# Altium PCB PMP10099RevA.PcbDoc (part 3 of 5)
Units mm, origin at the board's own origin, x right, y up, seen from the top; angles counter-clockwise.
Board outline 227.58 x 89.92 mm, 2 copper layers (Top Layer, Bottom Layer), stack 1.575 mm thick; 558 components, 261 nets, 1374 pads, 560 vias.
Unrouted connection lines stored in the file: 7.
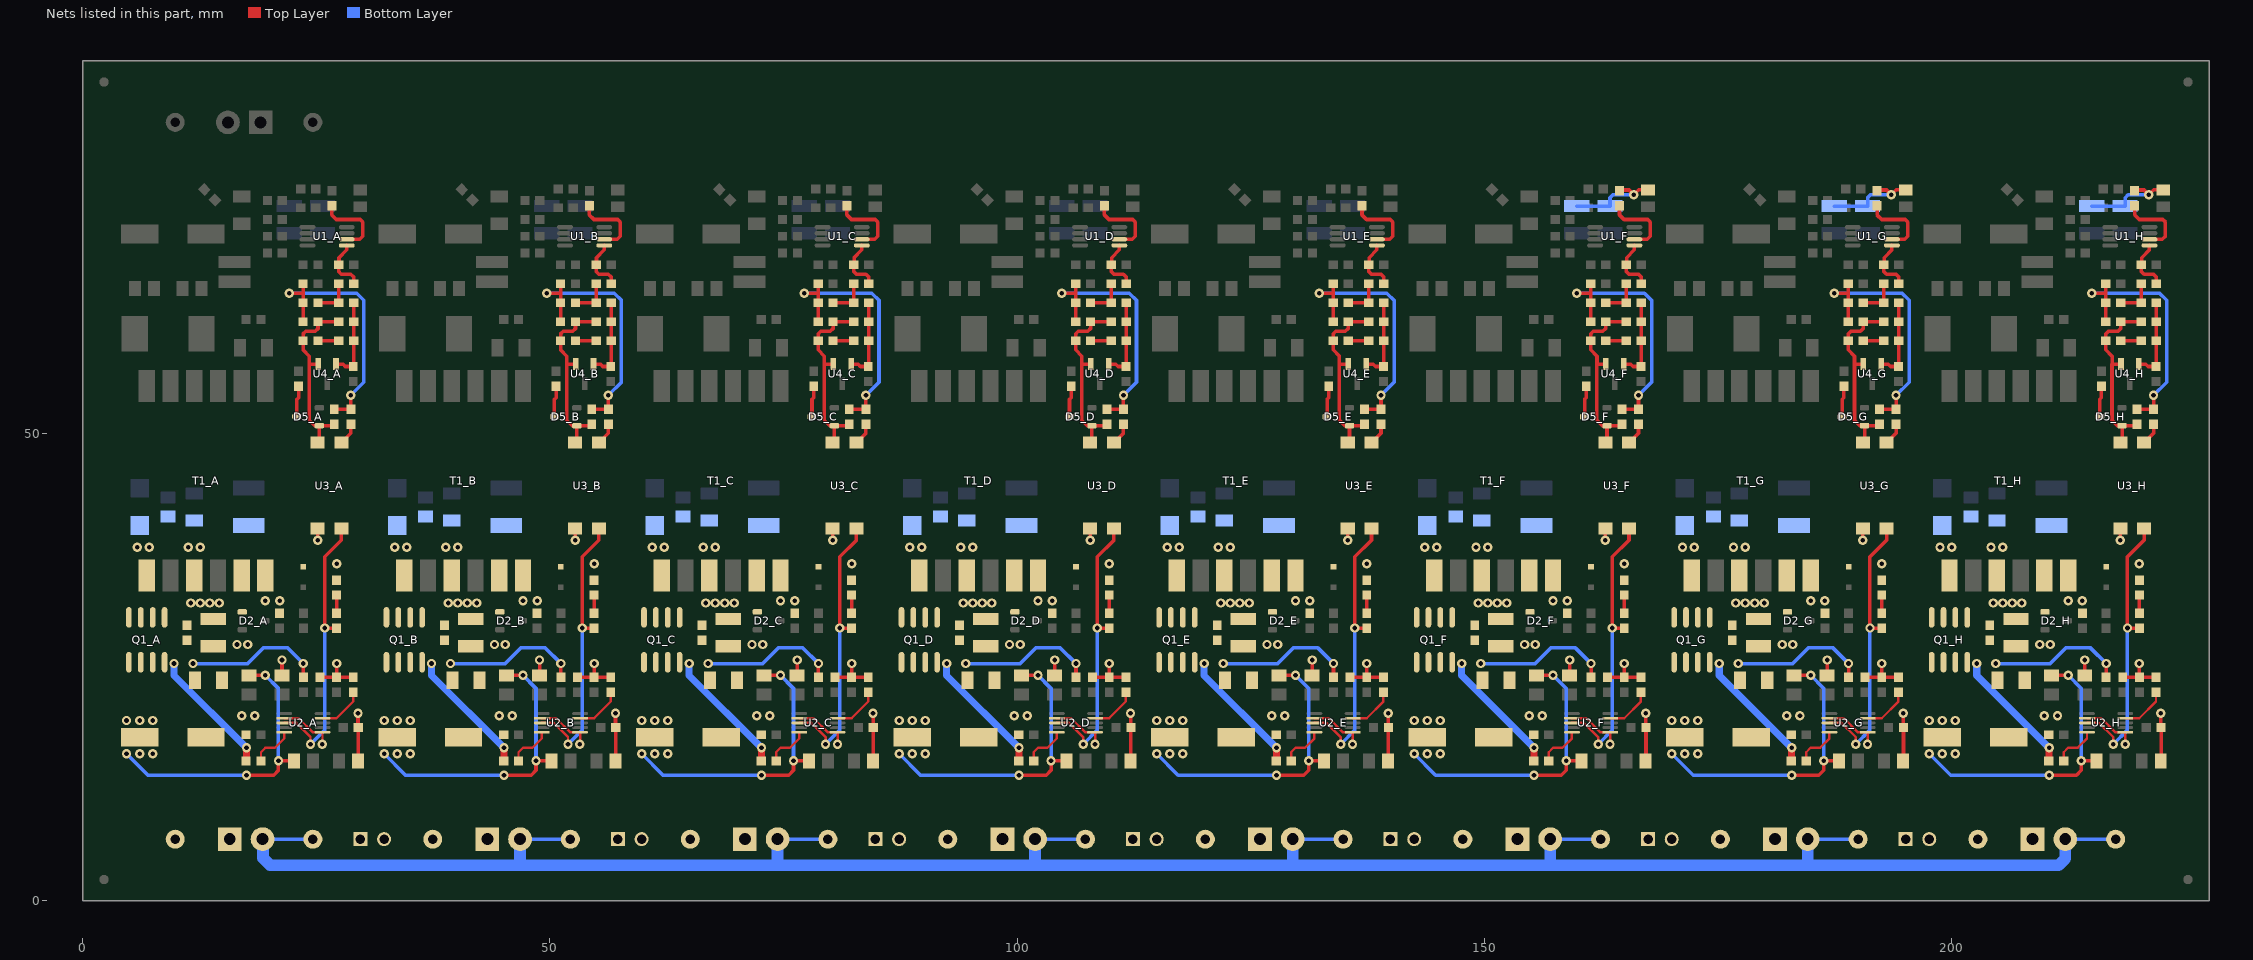
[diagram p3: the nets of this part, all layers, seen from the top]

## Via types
v1: diameter 1, hole 0.5, Top Layer to Bottom Layer, 560 vias

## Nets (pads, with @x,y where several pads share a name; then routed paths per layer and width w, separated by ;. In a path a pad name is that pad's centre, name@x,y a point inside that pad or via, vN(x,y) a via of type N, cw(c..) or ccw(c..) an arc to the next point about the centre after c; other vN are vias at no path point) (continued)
NetC19_F_1: C19_F.1 C20_F.1 C21_F.1 R17_F.1 | length 10.8
  Top Layer w0.381: R17_F.1@164.465,75.984 164.554,76.073 165.481,76.073 v1(165.989,75.565) 166.508,76.084 C21_F.1@167.513,76.084 ; C21_F.1@167.324,76.073 C21_F.1@167.413,75.984
  Bottom Layer w0.381: C19_F.1@159.893,74.348 C20_F.1@163.449,74.348 163.449,75.248 163.766,75.565 v1(165.989,75.565)
NetC19_G_1: C19_G.1 C20_G.1 C21_G.1 R17_G.1 | length 10.8
  Top Layer w0.381: R17_G.1@192.024,75.984 192.113,76.073 193.04,76.073 v1(193.548,75.565) 194.067,76.084 C21_G.1@195.072,76.084 ; C21_G.1@194.883,76.073 C21_G.1@194.972,75.984
  Bottom Layer w0.381: C19_G.1@187.452,74.348 C20_G.1@191.008,74.348 191.008,75.248 191.325,75.565 v1(193.548,75.565)
NetC19_H_1: C19_H.1 C20_H.1 C21_H.1 R17_H.1 | length 10.8
  Top Layer w0.381: R17_H.1@219.583,75.984 219.672,76.073 220.599,76.073 v1(221.107,75.565) 221.626,76.084 C21_H.1@222.631,76.084 ; C21_H.1@222.442,76.073 C21_H.1@222.531,75.984
  Bottom Layer w0.381: C19_H.1@215.011,74.348 C20_H.1@218.567,74.348 218.567,75.248 218.884,75.565 v1(221.107,75.565)
NetC22_A_1: C22_A.1 D5_A.1 R22_A.2 R23_A.1 R25_A.2 U3_A.2 U4_A.2 | length 19.9
  Top Layer w0.381: U3_A.2@25.146,49.062 25.33,49.246 D5_A.1@25.33,50.866 ; R23_A.1@25.184,61.976 25.184,61.252 24.892,60.96 23.876,60.96 23.584,60.668 R25_A.2@23.584,59.944 23.584,58.966 24.257,58.293 24.257,57.404 ; U4_A.2@25.212,57.438 24.291,57.438 24.257,57.404 ; R23_A.1@25.438,61.976 C22_A.1@27.394,61.976 C22_A.1@27.648,61.976 ; R22_A.2@26.774,50.866 D5_A.1@25.33,50.866 ; 24.257,57.404 24.255,57.402 24.255,51.437 24.826,50.866 D5_A.1@25.33,50.866
NetC22_A_2: C22_A.2 C23_A.2 R24_A.1 R27_A.2 U4_A.1 | length 8.9
  Top Layer w0.381: U4_A.1@27.112,57.438 27.878,57.438 28.128,57.188 R27_A.2@28.956,57.188 28.994,57.226 C23_A.2@28.994,59.944 28.994,61.722 C22_A.2@29.248,61.976 ; C22_A.2@28.994,61.976 R24_A.1@28.994,64.008
NetC22_B_1: C22_B.1 D5_B.1 R22_B.2 R23_B.1 R25_B.2 U3_B.2 U4_B.2 | length 19.9
  Top Layer w0.381: U3_B.2@52.705,49.062 52.889,49.246 D5_B.1@52.889,50.866 ; R23_B.1@52.743,61.976 52.743,61.252 52.451,60.96 51.435,60.96 51.143,60.668 R25_B.2@51.143,59.944 51.143,58.966 51.816,58.293 51.816,57.404 ; U4_B.2@52.771,57.438 51.85,57.438 51.816,57.404 ; R23_B.1@52.997,61.976 C22_B.1@54.953,61.976 C22_B.1@55.207,61.976 ; R22_B.2@54.333,50.866 D5_B.1@52.889,50.866 ; 51.816,57.404 51.814,57.402 51.814,51.437 52.385,50.866 D5_B.1@52.889,50.866
NetC22_B_2: C22_B.2 C23_B.2 R24_B.1 R27_B.2 U4_B.1 | length 8.9
  Top Layer w0.381: U4_B.1@54.671,57.438 55.437,57.438 55.687,57.188 R27_B.2@56.515,57.188 56.553,57.226 C23_B.2@56.553,59.944 56.553,61.722 C22_B.2@56.807,61.976 ; C22_B.2@56.553,61.976 R24_B.1@56.553,64.008
NetC22_C_1: C22_C.1 D5_C.1 R22_C.2 R23_C.1 R25_C.2 U3_C.2 U4_C.2 | length 19.9
  Top Layer w0.381: U3_C.2@80.264,49.062 80.448,49.246 D5_C.1@80.448,50.866 ; R23_C.1@80.302,61.976 80.302,61.252 80.01,60.96 78.994,60.96 78.702,60.668 R25_C.2@78.702,59.944 78.702,58.966 79.375,58.293 79.375,57.404 ; U4_C.2@80.33,57.438 79.409,57.438 79.375,57.404 ; R23_C.1@80.556,61.976 C22_C.1@82.512,61.976 C22_C.1@82.766,61.976 ; R22_C.2@81.892,50.866 D5_C.1@80.448,50.866 ; 79.375,57.404 79.373,57.402 79.373,51.437 79.944,50.866 D5_C.1@80.448,50.866
NetC22_C_2: C22_C.2 C23_C.2 R24_C.1 R27_C.2 U4_C.1 | length 8.9
  Top Layer w0.381: U4_C.1@82.23,57.438 82.996,57.438 83.246,57.188 R27_C.2@84.074,57.188 84.112,57.226 C23_C.2@84.112,59.944 84.112,61.722 C22_C.2@84.366,61.976 ; C22_C.2@84.112,61.976 R24_C.1@84.112,64.008
NetC22_D_1: C22_D.1 D5_D.1 R22_D.2 R23_D.1 R25_D.2 U3_D.2 U4_D.2 | length 19.9
  Top Layer w0.381: U3_D.2@107.823,49.062 108.007,49.246 D5_D.1@108.007,50.866 ; R23_D.1@107.861,61.976 107.861,61.252 107.569,60.96 106.553,60.96 106.261,60.668 R25_D.2@106.261,59.944 106.261,58.966 106.934,58.293 106.934,57.404 ; U4_D.2@107.889,57.438 106.968,57.438 106.934,57.404 ; R23_D.1@108.115,61.976 C22_D.1@110.071,61.976 C22_D.1@110.325,61.976 ; R22_D.2@109.451,50.866 D5_D.1@108.007,50.866 ; 106.934,57.404 106.932,57.402 106.932,51.437 107.503,50.866 D5_D.1@108.007,50.866
NetC22_D_2: C22_D.2 C23_D.2 R24_D.1 R27_D.2 U4_D.1 | length 8.9
  Top Layer w0.381: U4_D.1@109.789,57.438 110.555,57.438 110.805,57.188 R27_D.2@111.633,57.188 111.671,57.226 C23_D.2@111.671,59.944 111.671,61.722 C22_D.2@111.925,61.976 ; C22_D.2@111.671,61.976 R24_D.1@111.671,64.008
NetC22_E_1: C22_E.1 D5_E.1 R22_E.2 R23_E.1 R25_E.2 U3_E.2 U4_E.2 | length 19.9
  Top Layer w0.381: U3_E.2@135.382,49.062 135.566,49.246 D5_E.1@135.566,50.866 ; R23_E.1@135.42,61.976 135.42,61.252 135.128,60.96 134.112,60.96 133.82,60.668 R25_E.2@133.82,59.944 133.82,58.966 134.493,58.293 134.493,57.404 ; U4_E.2@135.448,57.438 134.527,57.438 134.493,57.404 ; R23_E.1@135.674,61.976 C22_E.1@137.63,61.976 C22_E.1@137.884,61.976 ; R22_E.2@137.01,50.866 D5_E.1@135.566,50.866 ; 134.493,57.404 134.491,57.402 134.491,51.437 135.062,50.866 D5_E.1@135.566,50.866
NetC22_E_2: C22_E.2 C23_E.2 R24_E.1 R27_E.2 U4_E.1 | length 8.9
  Top Layer w0.381: U4_E.1@137.348,57.438 138.114,57.438 138.364,57.188 R27_E.2@139.192,57.188 139.23,57.226 C23_E.2@139.23,59.944 139.23,61.722 C22_E.2@139.484,61.976 ; C22_E.2@139.23,61.976 R24_E.1@139.23,64.008
NetC22_F_1: C22_F.1 D5_F.1 R22_F.2 R23_F.1 R25_F.2 U3_F.2 U4_F.2 | length 19.9
  Top Layer w0.381: U3_F.2@162.941,49.062 163.125,49.246 D5_F.1@163.125,50.866 ; R23_F.1@162.979,61.976 162.979,61.252 162.687,60.96 161.671,60.96 161.379,60.668 R25_F.2@161.379,59.944 161.379,58.966 162.052,58.293 162.052,57.404 ; U4_F.2@163.007,57.438 162.086,57.438 162.052,57.404 ; R23_F.1@163.233,61.976 C22_F.1@165.189,61.976 C22_F.1@165.443,61.976 ; R22_F.2@164.569,50.866 D5_F.1@163.125,50.866 ; 162.052,57.404 162.05,57.402 162.05,51.437 162.621,50.866 D5_F.1@163.125,50.866
NetC22_F_2: C22_F.2 C23_F.2 R24_F.1 R27_F.2 U4_F.1 | length 8.9
  Top Layer w0.381: U4_F.1@164.907,57.438 165.673,57.438 165.923,57.188 R27_F.2@166.751,57.188 166.789,57.226 C23_F.2@166.789,59.944 166.789,61.722 C22_F.2@167.043,61.976 ; C22_F.2@166.789,61.976 R24_F.1@166.789,64.008
NetC22_G_1: C22_G.1 D5_G.1 R22_G.2 R23_G.1 R25_G.2 U3_G.2 U4_G.2 | length 19.9
  Top Layer w0.381: U3_G.2@190.5,49.062 190.684,49.246 D5_G.1@190.684,50.866 ; R23_G.1@190.538,61.976 190.538,61.252 190.246,60.96 189.23,60.96 188.938,60.668 R25_G.2@188.938,59.944 188.938,58.966 189.611,58.293 189.611,57.404 ; U4_G.2@190.566,57.438 189.645,57.438 189.611,57.404 ; R23_G.1@190.792,61.976 C22_G.1@192.748,61.976 C22_G.1@193.002,61.976 ; R22_G.2@192.128,50.866 D5_G.1@190.684,50.866 ; 189.611,57.404 189.609,57.402 189.609,51.437 190.18,50.866 D5_G.1@190.684,50.866
NetC22_G_2: C22_G.2 C23_G.2 R24_G.1 R27_G.2 U4_G.1 | length 8.9
  Top Layer w0.381: U4_G.1@192.466,57.438 193.232,57.438 193.482,57.188 R27_G.2@194.31,57.188 194.348,57.226 C23_G.2@194.348,59.944 194.348,61.722 C22_G.2@194.602,61.976 ; C22_G.2@194.348,61.976 R24_G.1@194.348,64.008
NetC22_H_1: C22_H.1 D5_H.1 R22_H.2 R23_H.1 R25_H.2 U3_H.2 U4_H.2 | length 19.9
  Top Layer w0.381: U3_H.2@218.059,49.062 218.243,49.246 D5_H.1@218.243,50.866 ; R23_H.1@218.097,61.976 218.097,61.252 217.805,60.96 216.789,60.96 216.497,60.668 R25_H.2@216.497,59.944 216.497,58.966 217.17,58.293 217.17,57.404 ; U4_H.2@218.125,57.438 217.204,57.438 217.17,57.404 ; R23_H.1@218.351,61.976 C22_H.1@220.307,61.976 C22_H.1@220.561,61.976 ; R22_H.2@219.687,50.866 D5_H.1@218.243,50.866 ; 217.17,57.404 217.168,57.402 217.168,51.437 217.739,50.866 D5_H.1@218.243,50.866
NetC22_H_2: C22_H.2 C23_H.2 R24_H.1 R27_H.2 U4_H.1 | length 8.9
  Top Layer w0.381: U4_H.1@220.025,57.438 220.791,57.438 221.041,57.188 R27_H.2@221.869,57.188 221.907,57.226 C23_H.2@221.907,59.944 221.907,61.722 C22_H.2@222.161,61.976 ; C22_H.2@221.907,61.976 R24_H.1@221.907,64.008
NetC23_A_1: C23_A.1 R25_A.1 | length 2.2
  Top Layer w0.381: R25_A.1@25.438,59.944 C23_A.1@27.648,59.944
NetC23_B_1: C23_B.1 R25_B.1 | length 2.2
  Top Layer w0.381: R25_B.1@52.997,59.944 C23_B.1@55.207,59.944
NetC23_C_1: C23_C.1 R25_C.1 | length 2.2
  Top Layer w0.381: R25_C.1@80.556,59.944 C23_C.1@82.766,59.944
NetC23_D_1: C23_D.1 R25_D.1 | length 2.2
  Top Layer w0.381: R25_D.1@108.115,59.944 C23_D.1@110.325,59.944
NetC23_E_1: C23_E.1 R25_E.1 | length 2.2
  Top Layer w0.381: R25_E.1@135.674,59.944 C23_E.1@137.884,59.944
NetC23_F_1: C23_F.1 R25_F.1 | length 2.2
  Top Layer w0.381: R25_F.1@163.233,59.944 C23_F.1@165.443,59.944
NetC23_G_1: C23_G.1 R25_G.1 | length 2.2
  Top Layer w0.381: R25_G.1@190.792,59.944 C23_G.1@193.002,59.944
NetC23_H_1: C23_H.1 R25_H.1 | length 2.2
  Top Layer w0.381: R25_H.1@218.351,59.944 C23_H.1@220.561,59.944
NetC24_A_1: C24_A.1 R26_A.1 | length 2
  Top Layer w0.381: R26_A.1@27.178,30.772 C24_A.1@27.178,32.728
NetC24_B_1: C24_B.1 R26_B.1 | length 2
  Top Layer w0.381: R26_B.1@54.737,30.772 C24_B.1@54.737,32.728
NetC24_C_1: C24_C.1 R26_C.1 | length 2
  Top Layer w0.381: R26_C.1@82.296,30.772 C24_C.1@82.296,32.728
NetC24_D_1: C24_D.1 R26_D.1 | length 2
  Top Layer w0.381: R26_D.1@109.855,30.772 C24_D.1@109.855,32.728
NetC24_E_1: C24_E.1 R26_E.1 | length 2
  Top Layer w0.381: R26_E.1@137.414,30.772 C24_E.1@137.414,32.728
NetC24_F_1: C24_F.1 R26_F.1 | length 2
  Top Layer w0.381: R26_F.1@164.973,30.772 C24_F.1@164.973,32.728
NetC24_G_1: C24_G.1 R26_G.1 | length 2
  Top Layer w0.381: R26_G.1@192.532,30.772 C24_G.1@192.532,32.728
NetC24_H_1: C24_H.1 R26_H.1 | length 2
  Top Layer w0.381: R26_H.1@220.091,30.772 C24_H.1@220.091,32.728
NetC26_A_1: C26_A.1 D5_A.3 | length 3.3
  Top Layer w0.381: D5_A.3@22.93,51.816 22.93,53.664 23.114,53.848 C26_A.1@23.114,55.08
NetC26_B_1: C26_B.1 D5_B.3 | length 3.3
  Top Layer w0.381: D5_B.3@50.489,51.816 50.489,53.664 50.673,53.848 C26_B.1@50.673,55.08
NetC26_C_1: C26_C.1 D5_C.3 | length 3.3
  Top Layer w0.381: D5_C.3@78.048,51.816 78.048,53.664 78.232,53.848 C26_C.1@78.232,55.08
NetC26_D_1: C26_D.1 D5_D.3 | length 3.3
  Top Layer w0.381: D5_D.3@105.607,51.816 105.607,53.664 105.791,53.848 C26_D.1@105.791,55.08
NetC26_E_1: C26_E.1 D5_E.3 | length 3.3
  Top Layer w0.381: D5_E.3@133.166,51.816 133.166,53.664 133.35,53.848 C26_E.1@133.35,55.08
NetC26_F_1: C26_F.1 D5_F.3 | length 3.3
  Top Layer w0.381: D5_F.3@160.725,51.816 160.725,53.664 160.909,53.848 C26_F.1@160.909,55.08
NetC26_G_1: C26_G.1 D5_G.3 | length 3.3
  Top Layer w0.381: D5_G.3@188.284,51.816 188.284,53.664 188.468,53.848 C26_G.1@188.468,55.08
NetC26_H_1: C26_H.1 D5_H.3 | length 3.3
  Top Layer w0.381: D5_H.3@215.843,51.816 215.843,53.664 216.027,53.848 C26_H.1@216.027,55.08
NetD1_A_2: D1_A.2 Q1_A.5 Q1_A.6 Q1_A.7 Q1_A.8 T1_A.1
  other v1: 5.842,37.846 7.112,37.846
NetD1_B_2: D1_B.2 Q1_B.5 Q1_B.6 Q1_B.7 Q1_B.8 T1_B.1
  other v1: 33.401,37.846 34.671,37.846
NetD1_C_2: D1_C.2 Q1_C.5 Q1_C.6 Q1_C.7 Q1_C.8 T1_C.1
  other v1: 60.96,37.846 62.23,37.846
NetD1_D_2: D1_D.2 Q1_D.5 Q1_D.6 Q1_D.7 Q1_D.8 T1_D.1
  other v1: 88.519,37.846 89.789,37.846
NetD1_E_2: D1_E.2 Q1_E.5 Q1_E.6 Q1_E.7 Q1_E.8 T1_E.1
  other v1: 116.078,37.846 117.348,37.846
NetD1_F_2: D1_F.2 Q1_F.5 Q1_F.6 Q1_F.7 Q1_F.8 T1_F.1
  other v1: 143.637,37.846 144.907,37.846
NetD1_G_2: D1_G.2 Q1_G.5 Q1_G.6 Q1_G.7 Q1_G.8 T1_G.1
  other v1: 171.196,37.846 172.466,37.846
NetD1_H_2: D1_H.2 Q1_H.5 Q1_H.6 Q1_H.7 Q1_H.8 T1_H.1
  other v1: 198.755,37.846 200.025,37.846
NetD2_A_1: D2_A.1 T1_A.5
NetD2_B_1: D2_B.1 T1_B.5
NetD2_C_1: D2_C.1 T1_C.5
NetD2_D_1: D2_D.1 T1_D.5
NetD2_E_1: D2_E.1 T1_E.5
NetD2_F_1: D2_F.1 T1_F.5
NetD2_G_1: D2_G.1 T1_G.5
NetD2_H_1: D2_H.1 T1_H.5
NetQ1_A_1: Q1_A.1 Q1_A.2 Q1_A.3 R15_A.2 R20_A.2 | length 14.7
  Top Layer w0.381: R15_A.2@23.622,23.914 v1(23.622,25.4)
  Bottom Layer w0.381: v1(11.811,25.4) 17.653,25.4 19.321,27.068 21.954,27.068 v1(23.622,25.4)
NetQ1_A_4: Q1_A.4 R13_A.2 | length 13.6
  Top Layer w0.762: R13_A.2@17.488,14.986 17.526,15.024 v1(17.526,16.383)
  Bottom Layer w0.762: v1(9.779,25.4) 9.779,24.13 v1(17.526,16.383)
NetQ1_B_1: Q1_B.1 Q1_B.2 Q1_B.3 R15_B.2 R20_B.2 | length 14.7
  Top Layer w0.381: R15_B.2@51.181,23.914 v1(51.181,25.4)
  Bottom Layer w0.381: v1(39.37,25.4) 45.212,25.4 46.88,27.068 49.513,27.068 v1(51.181,25.4)
NetQ1_B_4: Q1_B.4 R13_B.2 | length 13.6
  Top Layer w0.762: R13_B.2@45.047,14.986 45.085,15.024 v1(45.085,16.383)
  Bottom Layer w0.762: v1(37.338,25.4) 37.338,24.13 v1(45.085,16.383)
NetQ1_C_1: Q1_C.1 Q1_C.2 Q1_C.3 R15_C.2 R20_C.2 | length 14.7
  Top Layer w0.381: R15_C.2@78.74,23.914 v1(78.74,25.4)
  Bottom Layer w0.381: v1(66.929,25.4) 72.771,25.4 74.439,27.068 77.072,27.068 v1(78.74,25.4)
NetQ1_C_4: Q1_C.4 R13_C.2 | length 13.6
  Top Layer w0.762: R13_C.2@72.606,14.986 72.644,15.024 v1(72.644,16.383)
  Bottom Layer w0.762: v1(64.897,25.4) 64.897,24.13 v1(72.644,16.383)
NetQ1_D_1: Q1_D.1 Q1_D.2 Q1_D.3 R15_D.2 R20_D.2 | length 14.7
  Top Layer w0.381: R15_D.2@106.299,23.914 v1(106.299,25.4)
  Bottom Layer w0.381: v1(94.488,25.4) 100.33,25.4 101.998,27.068 104.631,27.068 v1(106.299,25.4)
NetQ1_D_4: Q1_D.4 R13_D.2 | length 13.6
  Top Layer w0.762: R13_D.2@100.165,14.986 100.203,15.024 v1(100.203,16.383)
  Bottom Layer w0.762: v1(92.456,25.4) 92.456,24.13 v1(100.203,16.383)
NetQ1_E_1: Q1_E.1 Q1_E.2 Q1_E.3 R15_E.2 R20_E.2 | length 14.7
  Top Layer w0.381: R15_E.2@133.858,23.914 v1(133.858,25.4)
  Bottom Layer w0.381: v1(122.047,25.4) 127.889,25.4 129.557,27.068 132.19,27.068 v1(133.858,25.4)
NetQ1_E_4: Q1_E.4 R13_E.2 | length 13.6
  Top Layer w0.762: R13_E.2@127.724,14.986 127.762,15.024 v1(127.762,16.383)
  Bottom Layer w0.762: v1(120.015,25.4) 120.015,24.13 v1(127.762,16.383)
NetQ1_F_1: Q1_F.1 Q1_F.2 Q1_F.3 R15_F.2 R20_F.2 | length 14.7
  Top Layer w0.381: R15_F.2@161.417,23.914 v1(161.417,25.4)
  Bottom Layer w0.381: v1(149.606,25.4) 155.448,25.4 157.116,27.068 159.749,27.068 v1(161.417,25.4)
NetQ1_F_4: Q1_F.4 R13_F.2 | length 13.6
  Top Layer w0.762: R13_F.2@155.283,14.986 155.321,15.024 v1(155.321,16.383)
  Bottom Layer w0.762: v1(147.574,25.4) 147.574,24.13 v1(155.321,16.383)
NetQ1_G_1: Q1_G.1 Q1_G.2 Q1_G.3 R15_G.2 R20_G.2 | length 14.7
  Top Layer w0.381: R15_G.2@188.976,23.914 v1(188.976,25.4)
  Bottom Layer w0.381: v1(177.165,25.4) 183.007,25.4 184.675,27.068 187.308,27.068 v1(188.976,25.4)
NetQ1_G_4: Q1_G.4 R13_G.2 | length 13.6
  Top Layer w0.762: R13_G.2@182.842,14.986 182.88,15.024 v1(182.88,16.383)
  Bottom Layer w0.762: v1(175.133,25.4) 175.133,24.13 v1(182.88,16.383)
NetQ1_H_1: Q1_H.1 Q1_H.2 Q1_H.3 R15_H.2 R20_H.2 | length 14.7
  Top Layer w0.381: R15_H.2@216.535,23.914 v1(216.535,25.4)
  Bottom Layer w0.381: v1(204.724,25.4) 210.566,25.4 212.234,27.068 214.867,27.068 v1(216.535,25.4)
NetQ1_H_4: Q1_H.4 R13_H.2 | length 13.6
  Top Layer w0.762: R13_H.2@210.401,14.986 210.439,15.024 v1(210.439,16.383)
  Bottom Layer w0.762: v1(202.692,25.4) 202.692,24.13 v1(210.439,16.383)
NetR11_A_1: R11_A.1 R18_A.2 U1_A.5 | length 5.5
  Top Layer w0.381: R11_A.1@27.394,68.072 27.394,67.348 27.686,67.056 28.702,67.056 28.994,66.764 R18_A.2@28.994,66.04 ; R11_A.1@27.432,68.288 27.432,68.834 28.262,69.664 U1_A.5@28.262,70.145
NetR11_B_1: R11_B.1 R18_B.2 U1_B.5 | length 5.5
  Top Layer w0.381: R11_B.1@54.953,68.072 54.953,67.348 55.245,67.056 56.261,67.056 56.553,66.764 R18_B.2@56.553,66.04 ; R11_B.1@54.991,68.288 54.991,68.834 55.821,69.664 U1_B.5@55.821,70.145
NetR11_C_1: R11_C.1 R18_C.2 U1_C.5 | length 5.5
  Top Layer w0.381: R11_C.1@82.512,68.072 82.512,67.348 82.804,67.056 83.82,67.056 84.112,66.764 R18_C.2@84.112,66.04 ; R11_C.1@82.55,68.288 82.55,68.834 83.38,69.664 U1_C.5@83.38,70.145
NetR11_D_1: R11_D.1 R18_D.2 U1_D.5 | length 5.5
  Top Layer w0.381: R11_D.1@110.071,68.072 110.071,67.348 110.363,67.056 111.379,67.056 111.671,66.764 R18_D.2@111.671,66.04 ; R11_D.1@110.109,68.288 110.109,68.834 110.939,69.664 U1_D.5@110.939,70.145
NetR11_E_1: R11_E.1 R18_E.2 U1_E.5 | length 5.5
  Top Layer w0.381: R11_E.1@137.63,68.072 137.63,67.348 137.922,67.056 138.938,67.056 139.23,66.764 R18_E.2@139.23,66.04 ; R11_E.1@137.668,68.288 137.668,68.834 138.498,69.664 U1_E.5@138.498,70.145
NetR11_F_1: R11_F.1 R18_F.2 U1_F.5 | length 5.5
  Top Layer w0.381: R11_F.1@165.189,68.072 165.189,67.348 165.481,67.056 166.497,67.056 166.789,66.764 R18_F.2@166.789,66.04 ; R11_F.1@165.227,68.288 165.227,68.834 166.057,69.664 U1_F.5@166.057,70.145
NetR11_G_1: R11_G.1 R18_G.2 U1_G.5 | length 5.5
  Top Layer w0.381: R11_G.1@192.748,68.072 192.748,67.348 193.04,67.056 194.056,67.056 194.348,66.764 R18_G.2@194.348,66.04 ; R11_G.1@192.786,68.288 192.786,68.834 193.616,69.664 U1_G.5@193.616,70.145
NetR11_H_1: R11_H.1 R18_H.2 U1_H.5 | length 5.5
  Top Layer w0.381: R11_H.1@220.307,68.072 220.307,67.348 220.599,67.056 221.615,67.056 221.907,66.764 R18_H.2@221.907,66.04 ; R11_H.1@220.345,68.288 220.345,68.834 221.175,69.664 U1_H.5@221.175,70.145
NetR12_A_1: R12_A.1 R16_A.1 R21_A.2 R22_A.1 R23_A.2 | length 27.9
  Top Layer w0.381: v1(22.098,65.024) 23.584,65.024 ; R23_A.2@23.584,61.976 R16_A.1@23.584,64.008 23.584,65.024 ; R12_A.1@23.584,66.04 23.584,65.024 ; R22_A.1@26.924,52.616 R21_A.2@28.702,52.616 v1(28.702,54.102)
  Bottom Layer w0.381: v1(22.098,65.024) 29.337,65.024 30.099,64.262 30.099,55.499 v1(28.702,54.102)
NetR12_B_1: R12_B.1 R16_B.1 R21_B.2 R22_B.1 R23_B.2 | length 27.9
  Top Layer w0.381: v1(49.657,65.024) 51.143,65.024 ; R23_B.2@51.143,61.976 R16_B.1@51.143,64.008 51.143,65.024 ; R12_B.1@51.143,66.04 51.143,65.024 ; R22_B.1@54.483,52.616 R21_B.2@56.261,52.616 v1(56.261,54.102)
  Bottom Layer w0.381: v1(49.657,65.024) 56.896,65.024 57.658,64.262 57.658,55.499 v1(56.261,54.102)
NetR12_C_1: R12_C.1 R16_C.1 R21_C.2 R22_C.1 R23_C.2 | length 27.9
  Top Layer w0.381: v1(77.216,65.024) 78.702,65.024 ; R23_C.2@78.702,61.976 R16_C.1@78.702,64.008 78.702,65.024 ; R12_C.1@78.702,66.04 78.702,65.024 ; R22_C.1@82.042,52.616 R21_C.2@83.82,52.616 v1(83.82,54.102)
  Bottom Layer w0.381: v1(77.216,65.024) 84.455,65.024 85.217,64.262 85.217,55.499 v1(83.82,54.102)
NetR12_D_1: R12_D.1 R16_D.1 R21_D.2 R22_D.1 R23_D.2 | length 27.9
  Top Layer w0.381: v1(104.775,65.024) 106.261,65.024 ; R23_D.2@106.261,61.976 R16_D.1@106.261,64.008 106.261,65.024 ; R12_D.1@106.261,66.04 106.261,65.024 ; R22_D.1@109.601,52.616 R21_D.2@111.379,52.616 v1(111.379,54.102)
  Bottom Layer w0.381: v1(104.775,65.024) 112.014,65.024 112.776,64.262 112.776,55.499 v1(111.379,54.102)
NetR12_E_1: R12_E.1 R16_E.1 R21_E.2 R22_E.1 R23_E.2 | length 27.9
  Top Layer w0.381: v1(132.334,65.024) 133.82,65.024 ; R23_E.2@133.82,61.976 R16_E.1@133.82,64.008 133.82,65.024 ; R12_E.1@133.82,66.04 133.82,65.024 ; R22_E.1@137.16,52.616 R21_E.2@138.938,52.616 v1(138.938,54.102)
  Bottom Layer w0.381: v1(132.334,65.024) 139.573,65.024 140.335,64.262 140.335,55.499 v1(138.938,54.102)
NetR12_F_1: R12_F.1 R16_F.1 R21_F.2 R22_F.1 R23_F.2 | length 27.9
  Top Layer w0.381: v1(159.893,65.024) 161.379,65.024 ; R23_F.2@161.379,61.976 R16_F.1@161.379,64.008 161.379,65.024 ; R12_F.1@161.379,66.04 161.379,65.024 ; R22_F.1@164.719,52.616 R21_F.2@166.497,52.616 v1(166.497,54.102)
  Bottom Layer w0.381: v1(159.893,65.024) 167.132,65.024 167.894,64.262 167.894,55.499 v1(166.497,54.102)
NetR12_G_1: R12_G.1 R16_G.1 R21_G.2 R22_G.1 R23_G.2 | length 27.9
  Top Layer w0.381: v1(187.452,65.024) 188.938,65.024 ; R23_G.2@188.938,61.976 R16_G.1@188.938,64.008 188.938,65.024 ; R12_G.1@188.938,66.04 188.938,65.024 ; R22_G.1@192.278,52.616 R21_G.2@194.056,52.616 v1(194.056,54.102)
  Bottom Layer w0.381: v1(187.452,65.024) 194.691,65.024 195.453,64.262 195.453,55.499 v1(194.056,54.102)
NetR12_H_1: R12_H.1 R16_H.1 R21_H.2 R22_H.1 R23_H.2 | length 27.9
  Top Layer w0.381: v1(215.011,65.024) 216.497,65.024 ; R23_H.2@216.497,61.976 R16_H.1@216.497,64.008 216.497,65.024 ; R12_H.1@216.497,66.04 216.497,65.024 ; R22_H.1@219.837,52.616 R21_H.2@221.615,52.616 v1(221.615,54.102)
  Bottom Layer w0.381: v1(215.011,65.024) 222.25,65.024 223.012,64.262 223.012,55.499 v1(221.615,54.102)
NetR13_A_1: R13_A.1 U2_A.5 | length 4.7
  Top Layer w0.254: R13_A.1@19.088,14.986 19.088,15.913 19.558,16.383 20.574,16.383 21.572,17.381 U2_A.5@21.572,18.05
NetR13_B_1: R13_B.1 U2_B.5 | length 4.7
  Top Layer w0.254: R13_B.1@46.647,14.986 46.647,15.913 47.117,16.383 48.133,16.383 49.131,17.381 U2_B.5@49.131,18.05
NetR13_C_1: R13_C.1 U2_C.5 | length 4.7
  Top Layer w0.254: R13_C.1@74.206,14.986 74.206,15.913 74.676,16.383 75.692,16.383 76.69,17.381 U2_C.5@76.69,18.05
NetR13_D_1: R13_D.1 U2_D.5 | length 4.7
  Top Layer w0.254: R13_D.1@101.765,14.986 101.765,15.913 102.235,16.383 103.251,16.383 104.249,17.381 U2_D.5@104.249,18.05
NetR13_E_1: R13_E.1 U2_E.5 | length 4.7
  Top Layer w0.254: R13_E.1@129.324,14.986 129.324,15.913 129.794,16.383 130.81,16.383 131.808,17.381 U2_E.5@131.808,18.05
NetR13_F_1: R13_F.1 U2_F.5 | length 4.7
  Top Layer w0.254: R13_F.1@156.883,14.986 156.883,15.913 157.353,16.383 158.369,16.383 159.367,17.381 U2_F.5@159.367,18.05
NetR13_G_1: R13_G.1 U2_G.5 | length 4.7
  Top Layer w0.254: R13_G.1@184.442,14.986 184.442,15.913 184.912,16.383 185.928,16.383 186.926,17.381 U2_G.5@186.926,18.05
NetR13_H_1: R13_H.1 U2_H.5 | length 4.7
  Top Layer w0.254: R13_H.1@212.001,14.986 212.001,15.913 212.471,16.383 213.487,16.383 214.485,17.381 U2_H.5@214.485,18.05
NetR16_A_2: R16_A.2 R18_A.1 R24_A.2 | length 4.2
  Top Layer w0.381: R16_A.2@25.184,64.008 R24_A.2@27.394,64.008 R18_A.1@27.394,66.04
NetR16_B_2: R16_B.2 R18_B.1 R24_B.2 | length 4.2
  Top Layer w0.381: R16_B.2@52.743,64.008 R24_B.2@54.953,64.008 R18_B.1@54.953,66.04
NetR16_C_2: R16_C.2 R18_C.1 R24_C.2 | length 4.2
  Top Layer w0.381: R16_C.2@80.302,64.008 R24_C.2@82.512,64.008 R18_C.1@82.512,66.04
NetR16_D_2: R16_D.2 R18_D.1 R24_D.2 | length 4.2
  Top Layer w0.381: R16_D.2@107.861,64.008 R24_D.2@110.071,64.008 R18_D.1@110.071,66.04
NetR16_E_2: R16_E.2 R18_E.1 R24_E.2 | length 4.2
  Top Layer w0.381: R16_E.2@135.42,64.008 R24_E.2@137.63,64.008 R18_E.1@137.63,66.04
NetR16_F_2: R16_F.2 R18_F.1 R24_F.2 | length 4.2
  Top Layer w0.381: R16_F.2@162.979,64.008 R24_F.2@165.189,64.008 R18_F.1@165.189,66.04
NetR16_G_2: R16_G.2 R18_G.1 R24_G.2 | length 4.2
  Top Layer w0.381: R16_G.2@190.538,64.008 R24_G.2@192.748,64.008 R18_G.1@192.748,66.04
NetR16_H_2: R16_H.2 R18_H.1 R24_H.2 | length 4.2
  Top Layer w0.381: R16_H.2@218.097,64.008 R24_H.2@220.307,64.008 R18_H.1@220.307,66.04
NetR17_A_2: R17_A.2 U1_A.6 | length 8
  Top Layer w0.381: R17_A.2@26.67,74.384 26.67,73.406 27.156,72.92 29.696,72.92 29.972,72.644 29.972,71.12 29.647,70.795 U1_A.6@28.262,70.795
NetR17_B_2: R17_B.2 U1_B.6 | length 8
  Top Layer w0.381: R17_B.2@54.229,74.384 54.229,73.406 54.715,72.92 57.255,72.92 57.531,72.644 57.531,71.12 57.206,70.795 U1_B.6@55.821,70.795
NetR17_C_2: R17_C.2 U1_C.6 | length 8
  Top Layer w0.381: R17_C.2@81.788,74.384 81.788,73.406 82.274,72.92 84.814,72.92 85.09,72.644 85.09,71.12 84.765,70.795 U1_C.6@83.38,70.795
NetR17_D_2: R17_D.2 U1_D.6 | length 8
  Top Layer w0.381: R17_D.2@109.347,74.384 109.347,73.406 109.833,72.92 112.373,72.92 112.649,72.644 112.649,71.12 112.324,70.795 U1_D.6@110.939,70.795
NetR17_E_2: R17_E.2 U1_E.6 | length 8
  Top Layer w0.381: R17_E.2@136.906,74.384 136.906,73.406 137.392,72.92 139.932,72.92 140.208,72.644 140.208,71.12 139.883,70.795 U1_E.6@138.498,70.795
NetR17_F_2: R17_F.2 U1_F.6 | length 8
  Top Layer w0.381: R17_F.2@164.465,74.384 164.465,73.406 164.951,72.92 167.491,72.92 167.767,72.644 167.767,71.12 167.442,70.795 U1_F.6@166.057,70.795
NetR17_G_2: R17_G.2 U1_G.6 | length 8
  Top Layer w0.381: R17_G.2@192.024,74.384 192.024,73.406 192.51,72.92 195.05,72.92 195.326,72.644 195.326,71.12 195.001,70.795 U1_G.6@193.616,70.795
NetR17_H_2: R17_H.2 U1_H.6 | length 8
  Top Layer w0.381: R17_H.2@219.583,74.384 219.583,73.406 220.069,72.92 222.609,72.92 222.885,72.644 222.885,71.12 222.56,70.795 U1_H.6@221.175,70.795
NetR19_A_2: R19_A.2 U2_A.9 | length 5
  Top Layer w0.254: U2_A.9@25.672,19.55 27.17,19.55 28.956,21.336 R19_A.2@28.956,22.314
NetR19_B_2: R19_B.2 U2_B.9 | length 5
  Top Layer w0.254: U2_B.9@53.231,19.55 54.729,19.55 56.515,21.336 R19_B.2@56.515,22.314
NetR19_C_2: R19_C.2 U2_C.9 | length 5
  Top Layer w0.254: U2_C.9@80.79,19.55 82.288,19.55 84.074,21.336 R19_C.2@84.074,22.314
NetR19_D_2: R19_D.2 U2_D.9 | length 5
  Top Layer w0.254: U2_D.9@108.349,19.55 109.847,19.55 111.633,21.336 R19_D.2@111.633,22.314
NetR19_E_2: R19_E.2 U2_E.9 | length 5
  Top Layer w0.254: U2_E.9@135.908,19.55 137.406,19.55 139.192,21.336 R19_E.2@139.192,22.314
NetR19_F_2: R19_F.2 U2_F.9 | length 5
  Top Layer w0.254: U2_F.9@163.467,19.55 164.965,19.55 166.751,21.336 R19_F.2@166.751,22.314
NetR19_G_2: R19_G.2 U2_G.9 | length 5
  Top Layer w0.254: U2_G.9@191.026,19.55 192.524,19.55 194.31,21.336 R19_G.2@194.31,22.314
NetR19_H_2: R19_H.2 U2_H.9 | length 5
  Top Layer w0.254: U2_H.9@218.585,19.55 220.083,19.55 221.869,21.336 R19_H.2@221.869,22.314
NetR21_A_1: R21_A.1 U3_A.1 | length 2.4
  Top Layer w0.381: U3_A.1@27.686,49.037 28.702,50.053 R21_A.1@28.702,51.016
NetR21_B_1: R21_B.1 U3_B.1 | length 2.4
  Top Layer w0.381: U3_B.1@55.245,49.037 56.261,50.053 R21_B.1@56.261,51.016
NetR21_C_1: R21_C.1 U3_C.1 | length 2.4
  Top Layer w0.381: U3_C.1@82.804,49.037 83.82,50.053 R21_C.1@83.82,51.016
NetR21_D_1: R21_D.1 U3_D.1 | length 2.4
  Top Layer w0.381: U3_D.1@110.363,49.037 111.379,50.053 R21_D.1@111.379,51.016
NetR21_E_1: R21_E.1 U3_E.1 | length 2.4
  Top Layer w0.381: U3_E.1@137.922,49.037 138.938,50.053 R21_E.1@138.938,51.016
NetR21_F_1: R21_F.1 U3_F.1 | length 2.4
  Top Layer w0.381: U3_F.1@165.481,49.037 166.497,50.053 R21_F.1@166.497,51.016
NetR21_G_1: R21_G.1 U3_G.1 | length 2.4
  Top Layer w0.381: U3_G.1@193.04,49.037 194.056,50.053 R21_G.1@194.056,51.016
NetR21_H_1: R21_H.1 U3_H.1 | length 2.4
  Top Layer w0.381: U3_H.1@220.599,49.037 221.615,50.053 R21_H.1@221.615,51.016
NetR26_A_2: R26_A.2 U2_A.3 U3_A.4 | length 29.9
  Top Layer w0.254: U2_A.3@21.572,19.05 22.86,19.05 24.384,17.526 v1(24.384,16.764)
  Top Layer w0.381: R26_A.2@27.178,29.172 25.946,29.172 v1(25.908,29.21) 25.908,36.83 27.686,38.608 U3_A.4@27.686,39.837
  Bottom Layer w0.381: v1(24.384,16.764) 25.908,18.288 v1(25.908,29.21)
NetR26_B_2: R26_B.2 U2_B.3 U3_B.4 | length 29.9
  Top Layer w0.254: U2_B.3@49.131,19.05 50.419,19.05 51.943,17.526 v1(51.943,16.764)
  Top Layer w0.381: R26_B.2@54.737,29.172 53.505,29.172 v1(53.467,29.21) 53.467,36.83 55.245,38.608 U3_B.4@55.245,39.837
  Bottom Layer w0.381: v1(51.943,16.764) 53.467,18.288 v1(53.467,29.21)
NetR26_C_2: R26_C.2 U2_C.3 U3_C.4 | length 29.9
  Top Layer w0.254: U2_C.3@76.69,19.05 77.978,19.05 79.502,17.526 v1(79.502,16.764)
  Top Layer w0.381: R26_C.2@82.296,29.172 81.064,29.172 v1(81.026,29.21) 81.026,36.83 82.804,38.608 U3_C.4@82.804,39.837
  Bottom Layer w0.381: v1(79.502,16.764) 81.026,18.288 v1(81.026,29.21)
NetR26_D_2: R26_D.2 U2_D.3 U3_D.4 | length 29.9
  Top Layer w0.254: U2_D.3@104.249,19.05 105.537,19.05 107.061,17.526 v1(107.061,16.764)
  Top Layer w0.381: R26_D.2@109.855,29.172 108.623,29.172 v1(108.585,29.21) 108.585,36.83 110.363,38.608 U3_D.4@110.363,39.837
  Bottom Layer w0.381: v1(107.061,16.764) 108.585,18.288 v1(108.585,29.21)
NetR26_E_2: R26_E.2 U2_E.3 U3_E.4 | length 29.9
  Top Layer w0.254: U2_E.3@131.808,19.05 133.096,19.05 134.62,17.526 v1(134.62,16.764)
  Top Layer w0.381: R26_E.2@137.414,29.172 136.182,29.172 v1(136.144,29.21) 136.144,36.83 137.922,38.608 U3_E.4@137.922,39.837
  Bottom Layer w0.381: v1(134.62,16.764) 136.144,18.288 v1(136.144,29.21)
NetR26_F_2: R26_F.2 U2_F.3 U3_F.4 | length 29.9
  Top Layer w0.254: U2_F.3@159.367,19.05 160.655,19.05 162.179,17.526 v1(162.179,16.764)
  Top Layer w0.381: R26_F.2@164.973,29.172 163.741,29.172 v1(163.703,29.21) 163.703,36.83 165.481,38.608 U3_F.4@165.481,39.837
  Bottom Layer w0.381: v1(162.179,16.764) 163.703,18.288 v1(163.703,29.21)
NetR26_G_2: R26_G.2 U2_G.3 U3_G.4 | length 29.9
  Top Layer w0.254: U2_G.3@186.926,19.05 188.214,19.05 189.738,17.526 v1(189.738,16.764)
  Top Layer w0.381: R26_G.2@192.532,29.172 191.3,29.172 v1(191.262,29.21) 191.262,36.83 193.04,38.608 U3_G.4@193.04,39.837
  Bottom Layer w0.381: v1(189.738,16.764) 191.262,18.288 v1(191.262,29.21)
NetR26_H_2: R26_H.2 U2_H.3 U3_H.4 | length 29.9
  Top Layer w0.254: U2_H.3@214.485,19.05 215.773,19.05 217.297,17.526 v1(217.297,16.764)
  Top Layer w0.381: R26_H.2@220.091,29.172 218.859,29.172 v1(218.821,29.21) 218.821,36.83 220.599,38.608 U3_H.4@220.599,39.837
  Bottom Layer w0.381: v1(217.297,16.764) 218.821,18.288 v1(218.821,29.21)
RTN: C1_A.2 C1_B.2 C1_C.2 C1_D.2 C1_E.2 C1_F.2 C1_G.2 C1_H.2 C2_A.2 C2_B.2 C2_C.2 C2_D.2 C2_E.2 C2_F.2 C2_G.2 C2_H.2 C3_A.2 C3_B.2 C3_C.2 C3_D.2 C3_E.2 C3_F.2 C3_G.2 C3_H.2 C10_A.2 C10_B.2 C10_C.2 C10_D.2 C10_E.2 C10_F.2 C10_G.2 C10_H.2 C11_A.2 C11_B.2 C11_C.2 C11_D.2 C11_E.2 C11_F.2 C11_G.2 C11_H.2 C15_A.2 C15_B.2 C15_C.2 C15_D.2 C15_E.2 C15_F.2 C15_G.2 C15_H.2 C16_A.2 C16_B.2 C16_C.2 C16_D.2 C16_E.2 C16_F.2 C16_G.2 C16_H.2 C17_A.2 C17_B.2 C17_C.2 C17_D.2 C17_E.2 C17_F.2 C17_G.2 C17_H.2 C18_A.2 C18_B.2 C18_C.2 C18_D.2 C18_E.2 C18_F.2 C18_G.2 C18_H.2 C24_A.2 C24_B.2 C24_C.2 C24_D.2 C24_E.2 C24_F.2 C24_G.2 C24_H.2 C25_A.2 C25_B.2 C25_C.2 C25_D.2 C25_E.2 C25_F.2 C25_G.2 C25_H.2 D4_A.2 D4_B.2 D4_C.2 D4_D.2 D4_E.2 D4_F.2 D4_G.2 D4_H.2 J1_A.2 J1_B.2 J1_C.2 J1_D.2 J1_E.2 J1_F.2 J1_G.2 J1_H.2 R7_A.1 R7_B.1 R7_C.1 R7_D.1 R7_E.1 R7_F.1 R7_G.1 R7_H.1 R19_A.1 R19_B.1 R19_C.1 R19_D.1 R19_E.1 R19_F.1 R19_G.1 R19_H.1 R20_A.1 R20_B.1 R20_C.1 R20_D.1 R20_E.1 R20_F.1 R20_G.1 R20_H.1 T1_A.6 T1_B.6 T1_C.6 T1_D.6 T1_E.6 T1_F.6 T1_G.6 T1_H.6 TP2_A.1 TP2_B.1 TP2_C.1 TP2_D.1 TP2_E.1 TP2_F.1 TP2_G.1 TP2_H.1 U2_A.2 U2_A.6 U2_B.2 U2_B.6 U2_C.2 U2_C.6 U2_D.2 U2_D.6 U2_E.2 U2_E.6 U2_F.2 U2_F.6 U2_G.2 U2_G.6 U2_H.2 U2_H.6 U3_A.3 U3_B.3 U3_C.3 U3_D.3 U3_E.3 U3_F.3 U3_G.3 U3_H.3 | length 409
  Top Layer w0.254: U2_A.2@21.572,19.55 23.122,19.55 24.638,18.034 25.656,18.034 U2_A.6@25.672,18.05 25.672,17.036 25.654,17.018 v1(25.654,16.764) ; U2_B.2@49.131,19.55 50.681,19.55 52.197,18.034 53.215,18.034 U2_B.6@53.231,18.05 53.231,17.036 53.213,17.018 v1(53.213,16.764) ; U2_C.2@76.69,19.55 78.24,19.55 79.756,18.034 80.774,18.034 U2_C.6@80.79,18.05 80.79,17.036 80.772,17.018 v1(80.772,16.764) ; U2_D.2@104.249,19.55 105.799,19.55 107.315,18.034 108.333,18.034 U2_D.6@108.349,18.05 108.349,17.036 108.331,17.018 v1(108.331,16.764) ; U2_E.2@131.808,19.55 133.358,19.55 134.874,18.034 135.892,18.034 U2_E.6@135.908,18.05 135.908,17.036 135.89,17.018 v1(135.89,16.764) ; U2_F.2@159.367,19.55 160.917,19.55 162.433,18.034 163.451,18.034 U2_F.6@163.467,18.05 163.467,17.036 163.449,17.018 v1(163.449,16.764) ; U2_G.2@186.926,19.55 188.476,19.55 189.992,18.034 191.01,18.034 U2_G.6@191.026,18.05 191.026,17.036 191.008,17.018 v1(191.008,16.764) ; U2_H.2@214.485,19.55 216.035,19.55 217.551,18.034 218.569,18.034 U2_H.6@218.585,18.05 218.585,17.036 218.567,17.018 v1(218.567,16.764)
  Top Layer w0.381: C17_A.2@17.488,17.78 C17_A.2@17.526,17.818 ; C10_A.2@21.336,24.13 v1(21.336,25.781) ; v1(25.146,38.608) U3_A.3@25.146,39.862 ; C18_A.2@25.4,23.914 C16_A.2@27.178,23.914 ; v1(27.178,25.4) C16_A.2@27.178,23.914 ; R19_A.1@28.956,23.914 C16_A.2@27.178,23.914 ; R7_A.1@29.464,15.456 R7_A.1@29.68,15.24 ; v1(29.464,20.066) 29.464,18.58 C15_A.2@29.502,18.542 R7_A.1@29.502,15.494 ; C17_B.2@45.047,17.78 C17_B.2@45.085,17.818 ; C10_B.2@48.895,24.13 v1(48.895,25.781) ; v1(52.705,38.608) U3_B.3@52.705,39.862 ; C18_B.2@52.959,23.914 C16_B.2@54.737,23.914 ; v1(54.737,25.4) C16_B.2@54.737,23.914 ; R19_B.1@56.515,23.914 C16_B.2@54.737,23.914 ; R7_B.1@57.023,15.456 R7_B.1@57.239,15.24 ; v1(57.023,20.066) 57.023,18.58 C15_B.2@57.061,18.542 R7_B.1@57.061,15.494 ; C17_C.2@72.606,17.78 C17_C.2@72.644,17.818 ; C10_C.2@76.454,24.13 v1(76.454,25.781) ; v1(80.264,38.608) U3_C.3@80.264,39.862 ; C18_C.2@80.518,23.914 C16_C.2@82.296,23.914 ; v1(82.296,25.4) C16_C.2@82.296,23.914 ; R19_C.1@84.074,23.914 C16_C.2@82.296,23.914 ; R7_C.1@84.582,15.456 R7_C.1@84.798,15.24 ; v1(84.582,20.066) 84.582,18.58 C15_C.2@84.62,18.542 R7_C.1@84.62,15.494 ; C17_D.2@100.165,17.78 C17_D.2@100.203,17.818 ; C10_D.2@104.013,24.13 v1(104.013,25.781) ; v1(107.823,38.608) U3_D.3@107.823,39.862 ; C18_D.2@108.077,23.914 C16_D.2@109.855,23.914 ; v1(109.855,25.4) C16_D.2@109.855,23.914 ; R19_D.1@111.633,23.914 C16_D.2@109.855,23.914 ; R7_D.1@112.141,15.456 R7_D.1@112.357,15.24 ; v1(112.141,20.066) 112.141,18.58 C15_D.2@112.179,18.542 R7_D.1@112.179,15.494 ; C17_E.2@127.724,17.78 C17_E.2@127.762,17.818 ; C10_E.2@131.572,24.13 v1(131.572,25.781) ; v1(135.382,38.608) U3_E.3@135.382,39.862 ; C18_E.2@135.636,23.914 C16_E.2@137.414,23.914 ; v1(137.414,25.4) C16_E.2@137.414,23.914 ; R19_E.1@139.192,23.914 C16_E.2@137.414,23.914 ; R7_E.1@139.7,15.456 R7_E.1@139.916,15.24 ; v1(139.7,20.066) 139.7,18.58 C15_E.2@139.738,18.542 R7_E.1@139.738,15.494 ; C17_F.2@155.283,17.78 C17_F.2@155.321,17.818 ; C10_F.2@159.131,24.13 v1(159.131,25.781) ; v1(162.941,38.608) U3_F.3@162.941,39.862 ; C18_F.2@163.195,23.914 C16_F.2@164.973,23.914 ; v1(164.973,25.4) C16_F.2@164.973,23.914 ; R19_F.1@166.751,23.914 C16_F.2@164.973,23.914 ; R7_F.1@167.259,15.456 R7_F.1@167.475,15.24 ; v1(167.259,20.066) 167.259,18.58 C15_F.2@167.297,18.542 R7_F.1@167.297,15.494 ; C17_G.2@182.842,17.78 C17_G.2@182.88,17.818 ; C10_G.2@186.69,24.13 v1(186.69,25.781) ; v1(190.5,38.608) U3_G.3@190.5,39.862 ; C18_G.2@190.754,23.914 C16_G.2@192.532,23.914 ; v1(192.532,25.4) C16_G.2@192.532,23.914 ; R19_G.1@194.31,23.914 C16_G.2@192.532,23.914 ; R7_G.1@194.818,15.456 R7_G.1@195.034,15.24 ; v1(194.818,20.066) 194.818,18.58 C15_G.2@194.856,18.542 R7_G.1@194.856,15.494 ; C17_H.2@210.401,17.78 C17_H.2@210.439,17.818 ; C10_H.2@214.249,24.13 v1(214.249,25.781) ; v1(218.059,38.608) U3_H.3@218.059,39.862 ; C18_H.2@218.313,23.914 C16_H.2@220.091,23.914 ; v1(220.091,25.4) C16_H.2@220.091,23.914 ; R19_H.1@221.869,23.914 C16_H.2@220.091,23.914 ; R7_H.1@222.377,15.456 R7_H.1@222.593,15.24 ; v1(222.377,20.066) 222.377,18.58 C15_H.2@222.415,18.542 R7_H.1@222.415,15.494
  Bottom Layer w0.381: J1_A.2@19.253,6.604 TP2_A.1@24.638,6.604 ; J1_B.2@46.812,6.604 TP2_B.1@52.197,6.604 ; J1_C.2@74.371,6.604 TP2_C.1@79.756,6.604 ; J1_D.2@101.93,6.604 TP2_D.1@107.315,6.604 ; J1_E.2@129.489,6.604 TP2_E.1@134.874,6.604 ; J1_F.2@157.048,6.604 TP2_F.1@162.433,6.604 ; J1_G.2@184.607,6.604 TP2_G.1@189.992,6.604 ; J1_H.2@212.166,6.604 TP2_H.1@217.551,6.604
  Bottom Layer w1.27: J1_A.2@19.253,6.604 19.304,6.553 19.304,4.572 20.015,3.861 ; 20.066,3.81 46.736,3.81 ; J1_B.2@46.812,6.604 46.812,3.886 46.736,3.81 ; J1_C.2@74.371,6.604 74.371,3.861 74.422,3.81 ; J1_D.2@101.93,6.604 101.93,3.886 101.854,3.81 ; J1_E.2@129.489,6.604 129.489,3.861 129.54,3.81 ; J1_F.2@157.048,6.604 157.048,3.886 156.972,3.81 ; J1_G.2@184.607,6.604 184.607,4.013 184.404,3.81 ; J1_H.2@212.166,6.604 212.166,4.521 211.455,3.81 184.404,3.81 ; 46.736,3.81 74.422,3.81 ; 74.422,3.81 101.854,3.81 ; 101.854,3.81 129.54,3.81 ; 129.54,3.81 156.972,3.81 ; 156.972,3.81 184.404,3.81
  other v1: 17.018,19.812 18.415,19.812 44.577,19.812 45.974,19.812 72.136,19.812 73.533,19.812 99.695,19.812 101.092,19.812 127.254,19.812 128.651,19.812 154.813,19.812 156.21,19.812 182.372,19.812 183.769,19.812 209.931,19.812 211.328,19.812 16.51,27.432 17.653,27.432 44.069,27.432 45.212,27.432 71.628,27.432 72.771,27.432 99.187,27.432 100.33,27.432 126.746,27.432 127.889,27.432 154.305,27.432 155.448,27.432 181.864,27.432 183.007,27.432 209.423,27.432 210.566,27.432 19.558,32.131 21.082,32.131 47.117,32.131 48.641,32.131 74.676,32.131 76.2,32.131 102.235,32.131 103.759,32.131 129.794,32.131 131.318,32.131 157.353,32.131 158.877,32.131 184.912,32.131 186.436,32.131 212.471,32.131 213.995,32.131 27.178,36.068 54.737,36.068 82.296,36.068 109.855,36.068 137.414,36.068 164.973,36.068 192.532,36.068 220.091,36.068
VIN: C1_A.1 C1_B.1 C1_C.1 C1_D.1 C1_E.1 C1_F.1 C1_G.1 C1_H.1 C2_A.1 C2_B.1 C2_C.1 C2_D.1 C2_E.1 C2_F.1 C2_G.1 C2_H.1 C3_A.1 C3_B.1 C3_C.1 C3_D.1 C3_E.1 C3_F.1 C3_G.1 C3_H.1 C4_A.1 C4_B.1 C4_C.1 C4_D.1 C4_E.1 C4_F.1 C4_G.1 C4_H.1 J1_A.1 J1_B.1 J1_C.1 J1_D.1 J1_E.1 J1_F.1 J1_G.1 J1_H.1 J2.1 J2.2 J3.1 J3.2 J4.1 J4.2 J5.1 J5.2 J6.1 J6.2 J7.1 J7.2 J8.1 J8.2 R1_A.2 R1_B.2 R1_C.2 R1_D.2 R1_E.2 R1_F.2 R1_G.2 R1_H.2 R4_A.2 R4_B.2 R4_C.2 R4_D.2 R4_E.2 R4_F.2 R4_G.2 R4_H.2 R5_A.2 R5_B.2 R5_C.2 R5_D.2 R5_E.2 R5_F.2 R5_G.2 R5_H.2 T1_A.3 T1_B.3 T1_C.3 T1_D.3 T1_E.3 T1_F.3 T1_G.3 T1_H.3 TP1_A.1 TP1_B.1 TP1_C.1 TP1_D.1 TP1_E.1 TP1_F.1 TP1_G.1 TP1_H.1 | length 252.6
  Top Layer w0.381: v1(17.526,13.462) 20.447,13.462 20.955,13.97 v1(20.955,14.986) R4_A.2@22.606,14.986 ; R5_A.2@17.78,24.13 v1(19.558,24.13) ; v1(45.085,13.462) 48.006,13.462 48.514,13.97 v1(48.514,14.986) R4_B.2@50.165,14.986 ; R5_B.2@45.339,24.13 v1(47.117,24.13) ; v1(72.644,13.462) 75.565,13.462 76.073,13.97 v1(76.073,14.986) R4_C.2@77.724,14.986 ; R5_C.2@72.898,24.13 v1(74.676,24.13) ; v1(100.203,13.462) 103.124,13.462 103.632,13.97 v1(103.632,14.986) R4_D.2@105.283,14.986 ; R5_D.2@100.457,24.13 v1(102.235,24.13) ; v1(127.762,13.462) 130.683,13.462 131.191,13.97 v1(131.191,14.986) R4_E.2@132.842,14.986 ; R5_E.2@128.016,24.13 v1(129.794,24.13) ; v1(155.321,13.462) 158.242,13.462 158.75,13.97 v1(158.75,14.986) R4_F.2@160.401,14.986 ; R5_F.2@155.575,24.13 v1(157.353,24.13) ; v1(182.88,13.462) 185.801,13.462 186.309,13.97 v1(186.309,14.986) R4_G.2@187.96,14.986 ; R5_G.2@183.134,24.13 v1(184.912,24.13) ; v1(210.439,13.462) 213.36,13.462 213.868,13.97 v1(213.868,14.986) R4_H.2@215.519,14.986 ; R5_H.2@210.693,24.13 v1(212.471,24.13)
  Bottom Layer w0.381: v1(4.699,15.748) 6.985,13.462 v1(17.526,13.462) ; v1(19.558,24.13) 20.955,22.733 v1(20.955,14.986) ; v1(32.258,15.748) 34.544,13.462 v1(45.085,13.462) ; v1(47.117,24.13) 48.514,22.733 v1(48.514,14.986) ; v1(59.817,15.748) 62.103,13.462 v1(72.644,13.462) ; v1(74.676,24.13) 76.073,22.733 v1(76.073,14.986) ; v1(87.376,15.748) 89.662,13.462 v1(100.203,13.462) ; v1(102.235,24.13) 103.632,22.733 v1(103.632,14.986) ; v1(114.935,15.748) 117.221,13.462 v1(127.762,13.462) ; v1(129.794,24.13) 131.191,22.733 v1(131.191,14.986) ; v1(142.494,15.748) 144.78,13.462 v1(155.321,13.462) ; v1(157.353,24.13) 158.75,22.733 v1(158.75,14.986) ; v1(170.053,15.748) 172.339,13.462 v1(182.88,13.462) ; v1(184.912,24.13) 186.309,22.733 v1(186.309,14.986) ; v1(197.612,15.748) 199.898,13.462 v1(210.439,13.462) ; v1(212.471,24.13) 213.868,22.733 v1(213.868,14.986)
  other v1: 6.096,15.748 7.493,15.748 33.655,15.748 35.052,15.748 61.214,15.748 62.611,15.748 88.773,15.748 90.17,15.748 116.332,15.748 117.729,15.748 143.891,15.748 145.288,15.748 171.45,15.748 172.847,15.748 199.009,15.748 200.406,15.748 4.699,19.304 6.096,19.304 7.493,19.304 32.258,19.304 33.655,19.304 35.052,19.304 59.817,19.304 61.214,19.304 62.611,19.304 87.376,19.304 88.773,19.304 90.17,19.304 114.935,19.304 116.332,19.304 117.729,19.304 142.494,19.304 143.891,19.304 145.288,19.304 170.053,19.304 171.45,19.304 172.847,19.304 197.612,19.304 199.009,19.304 200.406,19.304 11.557,31.877 12.573,31.877 13.589,31.877 14.605,31.877 39.116,31.877 40.132,31.877 41.148,31.877 42.164,31.877 66.675,31.877 67.691,31.877 68.707,31.877 69.723,31.877 94.234,31.877 95.25,31.877 96.266,31.877 97.282,31.877 121.793,31.877 122.809,31.877 123.825,31.877 124.841,31.877 149.352,31.877 150.368,31.877 151.384,31.877 152.4,31.877 176.911,31.877 177.927,31.877 178.943,31.877 179.959,31.877 204.47,31.877 205.486,31.877 206.502,31.877 207.518,31.877 11.303,37.846 12.573,37.846 38.862,37.846 40.132,37.846 66.421,37.846 67.691,37.846 93.98,37.846 95.25,37.846 121.539,37.846 122.809,37.846 149.098,37.846 150.368,37.846 176.657,37.846 177.927,37.846 204.216,37.846 205.486,37.846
